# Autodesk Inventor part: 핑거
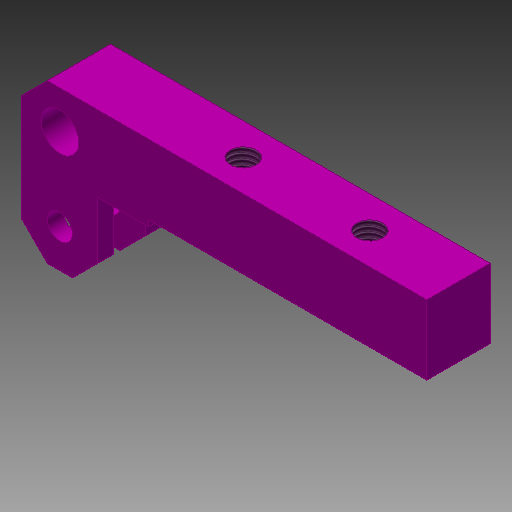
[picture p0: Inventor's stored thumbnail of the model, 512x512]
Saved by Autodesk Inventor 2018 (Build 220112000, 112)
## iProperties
Created: 2020-02
Part Number: 핑거
Material: 알루미늄 6061
Document SubType Name: Modeling
Designer: mduedu
Density: 1 g/cm^3
Appearance: 자홍색
Author: mduedu
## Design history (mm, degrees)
sketch "스케치1"
  geometry: L1 (0, 0)-(12, 0); L2 (64, 14)-(64, 25); L3 (64, 25)-(0, 25); L4 (0, 25)-(0, 0); L5 (12, 0)-(12, 13); L6 (12, 13)-(20, 13); L7 (64, 14)-(20, 14); L8 (20, 14)-(20, 13)
  constraints: 16 end point, 2 horizontal, 2 parallel, 1 perpendicular, 1 vertical
  dimensions: "d0" = 64 distance of L2.end L3.end; "d2" = 12 distance of L1.start L1.end; "d3" = 25 distance of L3.end L1.start; "d4" = 11 distance of L2.start L2.end; "d5" = 12 distance between parallel lines of L6 L3; "d6" = 44 distance of L2.start L7.end
extrude "돌출1" new body sketch "스케치1" stored distance "d7" = 10; taper "d8" = 0 deg
chamfer "모따기1" distance "d9" = 4; stored, may be unused: second distance "d10" = 2, angle "d11" = 45 deg
sketch "스케치2"
  geometry: L1 (2.5, -4)-(7.5, -4); L2 (7.5, -4)-(7.5, 9); L3 (7.5, 9)-(2.5, 9); L4 (2.5, 9)-(2.5, -4); L5 (10, 21)-(0, 21) reference; 2 further points
  constraints: 8 end point, 2 parallel, 1 coincident, 1 horizontal, 1 midpoint, 1 perpendicular
  dimensions: "d12" = 5 distance of L1.start L1.end; "d15" = 12 distance between parallel lines of L3 L5
extrude "돌출2" cut sketch "스케치2" extent not by distance; stored distance "d16" = 10; taper "d17" = 0 deg
sketch "스케치3"
  geometry: L1 (0, 4)-(0, 21) reference; L2 (4, 25)-(64, 25) reference; C1 r 2 at (6, 6); C2 r 3 at (6, 19); 1 further point
  constraints: 2 centre point, 1 vertical alignment
  dimensions: "d18" = 6 distance from line of C2.centre L1; "d19" = 6 distance from line of C2.centre L2; "d20" = 13 distance of C1.centre C2.centre; "d21" = 6 diameter of C2; "d22" = 4 diameter of C1
extrude "돌출3" cut sketch "스케치3" extent not by distance; stored distance "d23" = 10; taper "d24" = 0 deg
sketch "스케치4"
  geometry: L1 (0, 10)-(0, 0) reference; 3 further points
  constraints: 2 horizontal alignment
  dimensions: "d25" = 14 distance from line of point (-14, 5) L1; "d26" = 20 distance of point (-34, 5) point (-14, 5)
hole "구멍1" sketch "스케치4" at (-34, 5), (-14, 5) diameter "d27" = 4.134; stored, may be unused: countersink angle "d31" = 90 deg, drill point angle "d33" = 118 deg; dims "d28" = 6, "d29" = 4, "d30" = 2, "d32" = 8
node "솔리드1"
